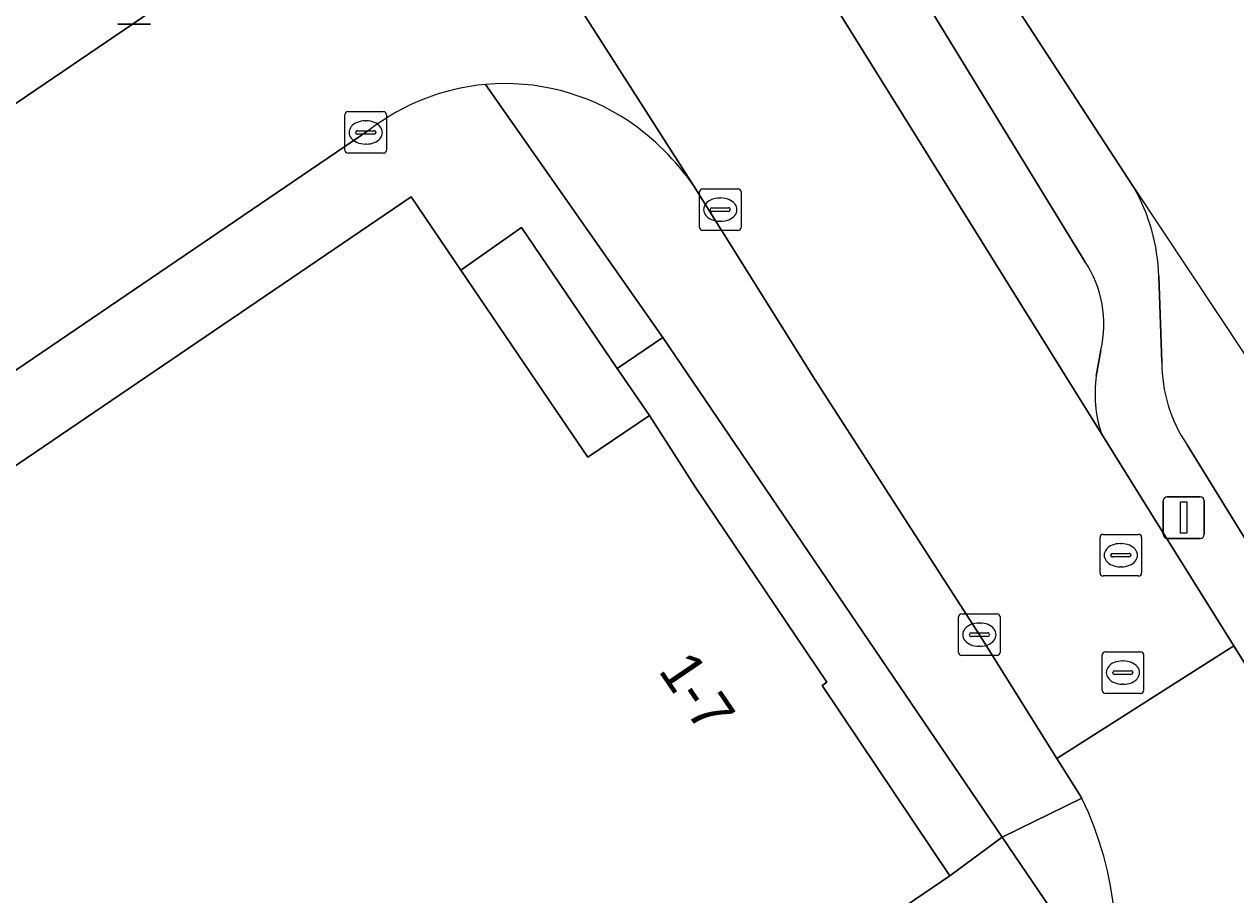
# Model space of a CAD drawing. Extents: x 160030 to 160839, y 385325 to 386450.
# Drawn here: x 160319.79 to 160348.93, y 386038.21 to 386059.14 of the extents above; entities that cross this region are included whole.
import ezdxf

# ---------------------------------------------------------------- set-up
doc = ezdxf.new("R2010")
doc.units = 0
for name, color, linetype in [('IMGEO_Erf', 7, 'Continuous'), ('IMGEO_Kolk', 7, 'Continuous'), ('IMGEO_Lichtmast', 7, 'Continuous'), ('IMGEO_Muur', 7, 'Continuous'), ('IMGEO_Pand', 7, 'Continuous'), ('IMGEO_Pand_nummerreeks', 7, 'Continuous'), ('IMGEO_Parkeervlak_open', 7, 'Continuous'), ('IMGEO_Rijbaan_lokaal_open', 7, 'Continuous'), ('IMGEO_Rioolput', 7, 'Continuous'), ('IMGEO_Voetpad_open', 7, 'Continuous')]:
    doc.layers.add(name, color=color, linetype=linetype)

msp = doc.modelspace()

# ---------------------------------------------------------------- linework, layer by layer
at = {"layer": 'IMGEO_Erf'}
for points in [[(160370.781, 386076.328), (160369.458, 386078.531), (160367.534, 386077.224), (160368.824, 386075.075), (160364.761, 386072.603), (160360.52, 386070.023), (160359.198, 386072.224), (160357.26, 386070.889), (160358.55, 386068.739), (160354.54, 386066.3), (160350.301, 386063.721), (160348.979, 386065.922), (160346.4, 386064.336), (160347.726, 386062.206), (160343.602, 386059.637), (160346.483, 386055.214)], [(160347.08, 386053.085), (160347.158, 386051.016)], [(160347.765, 386049.027), (160350.671, 386044.32), (160351.736, 386042.596)]]:
    msp.add_lwpolyline(points, dxfattribs=at)
for centre, radius, start, end in [((160342.575, 386052.97), 4.507, 1.4643, 29.8641), ((160350.628, 386050.988), 3.47, 179.5363, 214.4059)]:
    msp.add_arc(centre, radius, start, end, dxfattribs=at)
at = {"layer": 'IMGEO_Kolk'}
for p, q in [((160327.503, 386056.114), (160327.503, 386056.966)), ((160327.578, 386057.04), (160328.43, 386057.04)), ((160328.504, 386056.966), (160328.504, 386056.114)), ((160327.805, 386056.583), (160328.203, 386056.583)), ((160327.991, 386056.82), (160328.016, 386056.82)), ((160327.762, 386056.534), (160327.762, 386056.546)), ((160328.2, 386056.497), (160327.802, 386056.497)), ((160328.246, 386056.546), (160328.246, 386056.534)), ((160328.43, 386056.04), (160327.578, 386056.04)), ((160328.014, 386056.26), (160327.989, 386056.26)), ((160336.031, 386054.258), (160336.031, 386055.11)), ((160336.106, 386055.184), (160336.958, 386055.184)), ((160337.032, 386055.11), (160337.032, 386054.258)), ((160336.519, 386054.964), (160336.544, 386054.964)), ((160336.29, 386054.678), (160336.29, 386054.69)), ((160336.728, 386054.641), (160336.33, 386054.641)), ((160336.333, 386054.727), (160336.731, 386054.727)), ((160336.774, 386054.69), (160336.774, 386054.678)), ((160336.542, 386054.404), (160336.517, 386054.404)), ((160336.958, 386054.184), (160336.106, 386054.184)), ((160342.342, 386044.962), (160343.194, 386044.962)), ((160342.267, 386044.036), (160342.267, 386044.888)), ((160342.755, 386044.742), (160342.78, 386044.742)), ((160343.268, 386044.888), (160343.268, 386044.036)), ((160342.526, 386044.456), (160342.526, 386044.468)), ((160342.964, 386044.419), (160342.566, 386044.419)), ((160342.569, 386044.505), (160342.967, 386044.505)), ((160343.01, 386044.468), (160343.01, 386044.456)), ((160342.778, 386044.182), (160342.753, 386044.182)), ((160343.194, 386043.962), (160342.342, 386043.962))]:
    msp.add_line(p, q, dxfattribs=at)
for points in [[(160327.503, 386056.114), (160327.503, 386056.966)], [(160327.578, 386057.04), (160328.43, 386057.04)], [(160328.504, 386056.966), (160328.504, 386056.114)], [(160328.43, 386056.04), (160327.578, 386056.04)], [(160336.031, 386054.258), (160336.031, 386055.11)], [(160336.106, 386055.184), (160336.958, 386055.184)], [(160337.032, 386055.11), (160337.032, 386054.258)], [(160336.958, 386054.184), (160336.106, 386054.184)], [(160342.342, 386044.962), (160343.194, 386044.962)], [(160342.267, 386044.036), (160342.267, 386044.888)], [(160343.268, 386044.888), (160343.268, 386044.036)], [(160343.194, 386043.962), (160342.342, 386043.962)]]:
    msp.add_lwpolyline(points, dxfattribs=at)
for centre, radius, start, end in [((160327.58, 386056.964), 0.0765, 91.552, 178.448), ((160327.58, 386056.964), 0.0765, 91.552, 178.448), ((160328.428, 386056.964), 0.0765, 1.552, 88.448), ((160328.428, 386056.964), 0.0765, 1.552, 88.448), ((160327.802, 386056.543), 0.0403, 85.8775, 175.7526), ((160328.207, 386056.545), 0.0386, 1.7309, 96.639), ((160327.799, 386056.533), 0.0366, 178.938, 274.7102), ((160328.203, 386056.54), 0.043, 264.8664, 352.4533), ((160327.58, 386056.116), 0.0765, 181.552, 268.448), ((160327.58, 386056.116), 0.0765, 181.552, 268.448), ((160328.428, 386056.116), 0.0765, 271.552, 358.448), ((160328.428, 386056.116), 0.0765, 271.552, 358.448), ((160336.108, 386055.108), 0.0765, 91.552, 178.448), ((160336.108, 386055.108), 0.0765, 91.552, 178.448), ((160336.956, 386055.108), 0.0765, 1.552, 88.448), ((160336.956, 386055.108), 0.0765, 1.552, 88.448), ((160336.33, 386054.687), 0.0403, 85.8775, 175.7526), ((160336.327, 386054.677), 0.0366, 178.938, 274.7102), ((160336.731, 386054.684), 0.043, 264.8664, 352.4533), ((160336.735, 386054.689), 0.0386, 1.7309, 96.639), ((160336.108, 386054.26), 0.0765, 181.552, 268.448), ((160336.108, 386054.26), 0.0765, 181.552, 268.448), ((160336.956, 386054.26), 0.0765, 271.552, 358.448), ((160336.956, 386054.26), 0.0765, 271.552, 358.448), ((160342.344, 386044.886), 0.0765, 91.552, 178.448), ((160342.344, 386044.886), 0.0765, 91.552, 178.448), ((160343.192, 386044.886), 0.0765, 1.552, 88.448), ((160343.192, 386044.886), 0.0765, 1.552, 88.448), ((160342.566, 386044.465), 0.0403, 85.8775, 175.7526), ((160342.563, 386044.455), 0.0366, 178.938, 274.7102), ((160342.967, 386044.462), 0.043, 264.8664, 352.4533), ((160342.971, 386044.467), 0.0386, 1.7309, 96.639), ((160342.344, 386044.038), 0.0765, 181.552, 268.448), ((160342.344, 386044.038), 0.0765, 181.552, 268.448), ((160343.192, 386044.038), 0.0765, 271.552, 358.448), ((160343.192, 386044.038), 0.0765, 271.552, 358.448)]:
    msp.add_arc(centre, radius, start, end, dxfattribs=at)
for centre, major_axis, ratio, start_param, end_param in [((160327.99, 386056.54), (-0.387, 0.002), 0.722429, 4.712389, 7.853982), ((160328.015, 386056.54), (-0.39, 0.002), 0.717154, 1.570796, 4.712389), ((160336.518, 386054.684), (-0.387, 0.002), 0.722429, 4.712389, 7.853982), ((160336.543, 386054.684), (-0.39, 0.002), 0.717154, 1.570796, 4.712389), ((160342.754, 386044.462), (-0.387, 0.002), 0.722429, 4.712389, 7.853982), ((160342.779, 386044.462), (-0.39, 0.002), 0.717154, 1.570796, 4.712389)]:
    msp.add_ellipse(centre, major_axis=major_axis, ratio=ratio, start_param=start_param, end_param=end_param, dxfattribs=at)
at = {"layer": 'IMGEO_Lichtmast'}
for p, q in [((160322.825, 386059.142), (160322.035, 386059.142)), ((160322.035, 386059.142), (160322.825, 386059.142)), ((160347.188, 386046.878), (160347.188, 386047.678)), ((160347.188, 386047.678), (160347.188, 386046.878)), ((160347.288, 386047.778), (160348.078, 386047.778)), ((160348.078, 386047.778), (160347.288, 386047.778)), ((160348.178, 386047.678), (160348.178, 386046.878)), ((160348.178, 386046.878), (160348.178, 386047.678)), ((160348.078, 386046.778), (160347.288, 386046.778)), ((160347.288, 386046.778), (160348.078, 386046.778))]:
    msp.add_line(p, q, dxfattribs=at)
msp.add_lwpolyline([(160347.608, 386047.653), (160347.758, 386047.653), (160347.758, 386046.903), (160347.608, 386046.903), (160347.608, 386047.653)], dxfattribs=at)
for centre, start, end in [((160347.288, 386047.678), 90, 180), ((160347.288, 386047.678), 90, 180), ((160348.078, 386047.678), 0, 90), ((160348.078, 386047.678), 360, 90), ((160347.288, 386046.878), 180, 270), ((160347.288, 386046.878), 180, 270), ((160348.078, 386046.878), 270, 0), ((160348.078, 386046.878), 270, 0)]:
    msp.add_arc(centre, 0.1, start, end, dxfattribs=at)
at = {"layer": 'IMGEO_Muur'}
for points in [[(160343.602, 386059.637), (160346.483, 386055.214)], [(160346.483, 386055.214), (160349.158, 386051.183)]]:
    msp.add_lwpolyline(points, dxfattribs=at)
at = {"layer": 'IMGEO_Pand'}
msp.add_lwpolyline([(160312.523, 386018.623), (160319.794, 386023.564), (160319.86, 386023.609), (160318.884, 386025.58), (160320.375, 386026.606), (160321.617, 386024.801), (160323.443, 386026.038), (160331.231, 386031.313), (160342.054, 386038.664), (160338.986, 386043.242), (160339.1, 386043.322), (160335.927, 386048.015), (160334.826, 386049.73), (160333.35, 386048.728), (160332.578, 386049.864), (160330.293, 386053.228), (160329.094, 386054.994), (160265.499, 386011.79)], dxfattribs=at)
at = {"layer": 'IMGEO_Parkeervlak_open'}
for points in [[(160330.953, 386073.039), (160337.757, 386062.058), (160345.695, 386049.312)], [(160345.306, 386053.436), (160338.728, 386064.177)], [(160345.577, 386050.681), (160345.689, 386051.307)]]:
    msp.add_lwpolyline(points, dxfattribs=at)
for centre, radius, start, end in [((160343.035, 386051.929), 2.726, 346.8193, 33.5771), ((160348.681, 386050.259), 3.132, 172.2566, 197.5962)]:
    msp.add_arc(centre, radius, start, end, dxfattribs=at)
at = {"layer": 'IMGEO_Rijbaan_lokaal_open'}
for points in [[(160327.523, 386068.337), (160335.889, 386055.264), (160338.797, 386050.618), (160342.768, 386044.462), (160344.631, 386041.482), (160348.891, 386044.19), (160347.11, 386047.04), (160346.132, 386048.61), (160345.695, 386049.312), (160337.757, 386062.058)], [(160335.889, 386055.264), (160327.523, 386068.337)], [(160325.342, 386061.172), (160323.666, 386060.015), (160315.833, 386054.695), (160308.389, 386049.542), (160302.814, 386045.834), (160265.416, 386020.437), (160263.212, 386018.961), (160262.779, 386018.671)], [(160265.152, 386013.927), (160289.489, 386030.427), (160310.109, 386044.387), (160328.103, 386056.609)], [(160350.013, 386042.398), (160349.237, 386043.638), (160348.891, 386044.19), (160344.631, 386041.482), (160345.233, 386040.526)]]:
    msp.add_lwpolyline(points, dxfattribs=at)
for centre, radius, start, end in [((160331.357, 386052.378), 5.338, 95.0555, 127.5647), ((160331.356, 386052.375), 5.34, 56.1425, 95.0347), ((160330.873, 386051.767), 6.114, 34.8813, 55.5617), ((160337.862, 386036.949), 8.193, 304.8353, 25.8863)]:
    msp.add_arc(centre, radius, start, end, dxfattribs=at)
at = {"layer": 'IMGEO_Rioolput'}
for p, q in [((160345.669, 386045.947), (160345.669, 386046.799)), ((160345.744, 386046.873), (160346.596, 386046.873)), ((160346.157, 386046.653), (160346.182, 386046.653)), ((160346.67, 386046.799), (160346.67, 386045.947)), ((160345.928, 386046.367), (160345.928, 386046.379)), ((160345.971, 386046.416), (160346.369, 386046.416)), ((160346.412, 386046.379), (160346.412, 386046.367)), ((160346.366, 386046.33), (160345.968, 386046.33)), ((160346.18, 386046.093), (160346.155, 386046.093)), ((160346.596, 386045.873), (160345.744, 386045.873)), ((160345.793, 386044.05), (160346.645, 386044.05)), ((160345.718, 386043.124), (160345.718, 386043.976)), ((160346.206, 386043.83), (160346.231, 386043.83)), ((160346.719, 386043.976), (160346.719, 386043.124)), ((160345.977, 386043.544), (160345.977, 386043.556)), ((160346.415, 386043.507), (160346.017, 386043.507)), ((160346.02, 386043.593), (160346.418, 386043.593)), ((160346.461, 386043.556), (160346.461, 386043.544)), ((160346.229, 386043.27), (160346.204, 386043.27)), ((160346.645, 386043.05), (160345.793, 386043.05))]:
    msp.add_line(p, q, dxfattribs=at)
for points in [[(160345.669, 386045.947), (160345.669, 386046.799)], [(160345.744, 386046.873), (160346.596, 386046.873)], [(160346.67, 386046.799), (160346.67, 386045.947)], [(160346.596, 386045.873), (160345.744, 386045.873)], [(160345.793, 386044.05), (160346.645, 386044.05)], [(160345.718, 386043.124), (160345.718, 386043.976)], [(160346.719, 386043.976), (160346.719, 386043.124)], [(160346.645, 386043.05), (160345.793, 386043.05)]]:
    msp.add_lwpolyline(points, dxfattribs=at)
for centre, radius, start, end in [((160345.746, 386046.797), 0.0765, 91.552, 178.448), ((160345.746, 386046.797), 0.0765, 91.552, 178.448), ((160346.594, 386046.797), 0.0765, 1.552, 88.448), ((160346.594, 386046.797), 0.0765, 1.552, 88.448), ((160345.968, 386046.376), 0.0403, 85.8775, 175.7526), ((160345.965, 386046.366), 0.0366, 178.938, 274.7102), ((160346.369, 386046.373), 0.043, 264.8664, 352.4533), ((160346.373, 386046.378), 0.0386, 1.7309, 96.639), ((160345.746, 386045.949), 0.0765, 181.552, 268.448), ((160345.746, 386045.949), 0.0765, 181.552, 268.448), ((160346.594, 386045.949), 0.0765, 271.552, 358.448), ((160346.594, 386045.949), 0.0765, 271.552, 358.448), ((160345.795, 386043.974), 0.0765, 91.552, 178.448), ((160345.795, 386043.974), 0.0765, 91.552, 178.448), ((160346.643, 386043.974), 0.0765, 1.552, 88.448), ((160346.643, 386043.974), 0.0765, 1.552, 88.448), ((160346.017, 386043.553), 0.0403, 85.8775, 175.7526), ((160346.014, 386043.543), 0.0366, 178.938, 274.7102), ((160346.418, 386043.55), 0.043, 264.8664, 352.4533), ((160346.422, 386043.555), 0.0386, 1.7309, 96.639), ((160345.795, 386043.126), 0.0765, 181.552, 268.448), ((160345.795, 386043.126), 0.0765, 181.552, 268.448), ((160346.643, 386043.126), 0.0765, 271.552, 358.448), ((160346.643, 386043.126), 0.0765, 271.552, 358.448)]:
    msp.add_arc(centre, radius, start, end, dxfattribs=at)
for centre, major_axis, ratio, start_param, end_param in [((160346.156, 386046.373), (-0.387, 0.002), 0.722429, 4.712389, 7.853982), ((160346.181, 386046.373), (-0.39, 0.002), 0.717154, 1.570796, 4.712389), ((160346.205, 386043.55), (-0.387, 0.002), 0.722429, 4.712389, 7.853982), ((160346.23, 386043.55), (-0.39, 0.002), 0.717154, 1.570796, 4.712389)]:
    msp.add_ellipse(centre, major_axis=major_axis, ratio=ratio, start_param=start_param, end_param=end_param, dxfattribs=at)
at = {"layer": 'IMGEO_Voetpad_open'}
for points in [[(160356.119, 386126.467), (160355.583, 386125.97), (160313.388, 386099.731), (160312.51, 386101.101), (160306.39, 386097.366), (160307.246, 386095.986), (160326.368, 386065.167), (160324.593, 386064.084), (160318.325, 386060.184), (160309.448, 386054.767), (160307.413, 386053.524), (160306.13, 386052.646), (160307.267, 386051.171), (160308.389, 386049.542), (160315.833, 386054.695), (160323.666, 386060.015)], [(160346.483, 386055.214), (160343.602, 386059.637), (160342.276, 386061.767), (160341.518, 386063.044), (160340.233, 386065.107), (160336.764, 386070.723)], [(160335.528, 386069.358), (160338.728, 386064.177), (160345.306, 386053.436)], [(160329.094, 386054.994), (160330.293, 386053.228), (160331.749, 386054.258), (160334.054, 386050.866), (160335.152, 386051.612), (160330.887, 386057.695)], [(160330.887, 386057.695), (160335.152, 386051.612), (160343.316, 386039.594), (160345.233, 386040.526), (160344.631, 386041.482), (160342.768, 386044.462), (160338.797, 386050.618)], [(160328.103, 386056.609), (160310.109, 386044.387), (160289.489, 386030.427), (160265.152, 386013.927), (160265.499, 386011.79), (160329.094, 386054.994)], [(160338.797, 386050.618), (160335.889, 386055.264)], [(160347.158, 386051.016), (160347.08, 386053.085)], [(160345.689, 386051.307), (160345.577, 386050.681)], [(160345.695, 386049.312), (160346.132, 386048.61), (160347.11, 386047.04), (160348.891, 386044.19), (160349.237, 386043.638), (160350.671, 386044.32), (160347.765, 386049.027)], [(160345.233, 386040.526), (160343.316, 386039.594), (160344.638, 386037.648), (160289.221, 386000), (160275.764, 385990.858), (160274.499, 385992.721), (160272.127, 385991.391), (160272.708, 385990.505)], [(160289.221, 386000), (160344.638, 386037.648), (160343.316, 386039.594), (160342.054, 386038.664), (160331.231, 386031.313), (160323.443, 386026.038), (160321.617, 386024.801), (160319.86, 386023.609), (160319.794, 386023.564), (160312.523, 386018.623), (160309.45, 386016.571), (160303.287, 386012.365), (160303.18, 386012.291), (160300.183, 386010.237), (160299.306, 386009.642), (160292.906, 386005.297)]]:
    msp.add_lwpolyline(points, dxfattribs=at)
for points in [[(160331.749, 386054.258), (160330.293, 386053.228), (160332.578, 386049.864), (160333.35, 386048.728), (160334.826, 386049.73), (160334.054, 386050.866)], [(160335.152, 386051.612), (160334.054, 386050.866), (160334.826, 386049.73), (160335.927, 386048.015), (160339.1, 386043.322), (160338.986, 386043.242), (160342.054, 386038.664), (160343.316, 386039.594)]]:
    msp.add_lwpolyline(points, close=True, dxfattribs=at)
for centre, radius, start, end in [((160331.357, 386052.378), 5.338, 95.0555, 127.5647), ((160331.356, 386052.375), 5.34, 56.1425, 95.0347), ((160330.873, 386051.767), 6.114, 34.8813, 55.5617), ((160342.575, 386052.97), 4.507, 1.4643, 29.8641), ((160343.035, 386051.929), 2.726, 346.8193, 33.5771), ((160350.628, 386050.988), 3.47, 179.5363, 214.4059), ((160348.681, 386050.259), 3.132, 172.2566, 197.5962), ((160337.862, 386036.949), 8.193, 304.8353, 25.8863)]:
    msp.add_arc(centre, radius, start, end, dxfattribs=at)

# ---------------------------------------------------------------- texts
at = {"layer": 'IMGEO_Pand_nummerreeks'}
msp.add_text('1-7', height=1, rotation=304.1882, dxfattribs=at).set_placement((160335.025, 386043.6))

doc.saveas('drawing.dxf')
